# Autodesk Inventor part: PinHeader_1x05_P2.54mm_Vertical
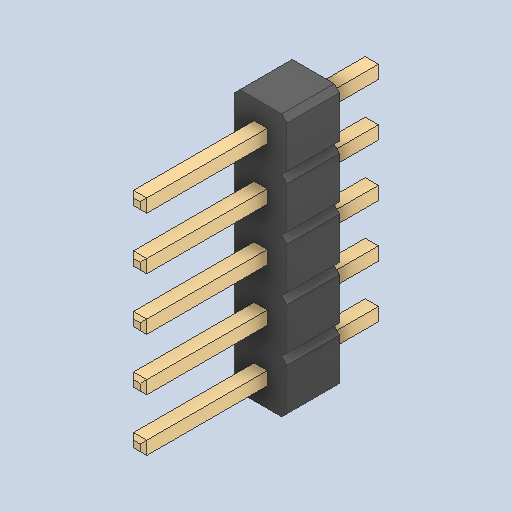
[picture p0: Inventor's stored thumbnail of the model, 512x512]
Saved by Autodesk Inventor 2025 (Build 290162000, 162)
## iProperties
Created: 2026-09
Part Number: PinHeader_1x05_P2.54mm_Vertical
Material: Generic
Document SubType Name: Modeling
Designer: Leonardo
Density: 1 g/cm^3
Appearance: Default
Author: Leonardo
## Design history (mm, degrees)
feature "Base1"
body "Solid1"
